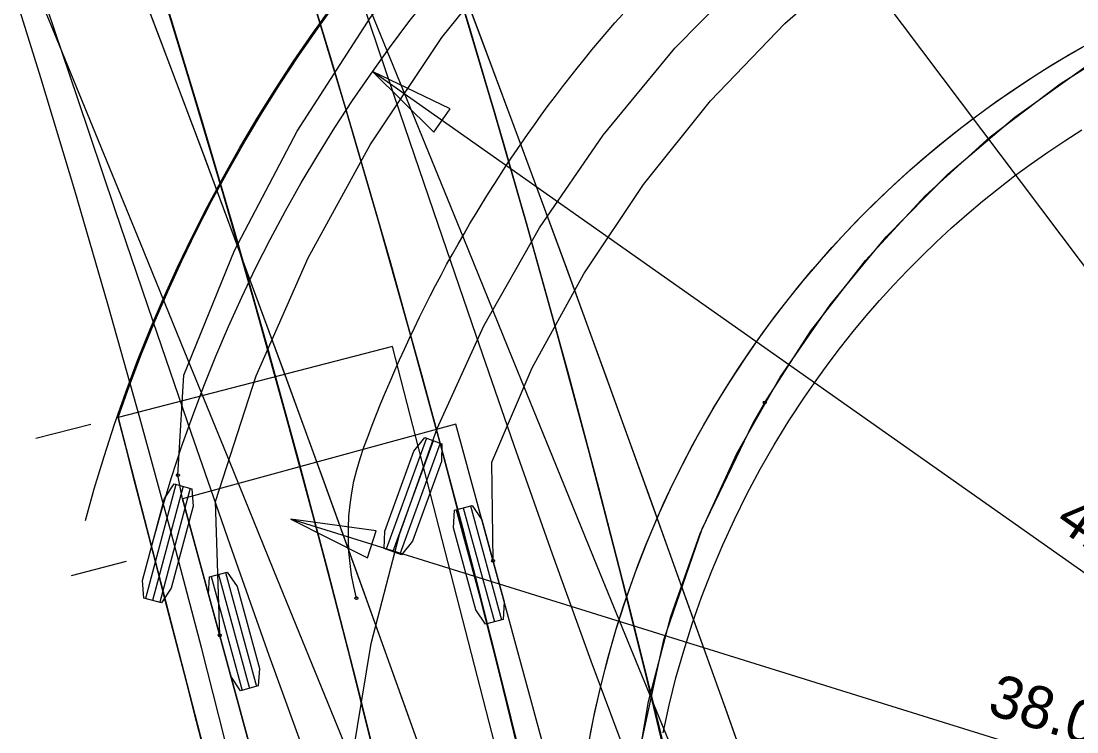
# Model space of a CAD drawing. Extents: x 916040 to 917457, y 328936 to 330267.
# Drawn here: x 916654.52 to 916684.33, y 329799.1 to 329819.17 of the extents above; entities that cross this region are included whole.
import ezdxf

# ---------------------------------------------------------------- set-up
doc = ezdxf.new("R2010")
doc.units = 0
for name, color, linetype in [('EB_LeftontoManchester_WB67', 7, 'Continuous'), ('EB_LeftontoManchester_WB67_v2', 7, 'Continuous'), ('NB_ThruontoManchester_WB67', 7, 'Continuous'), ('SU_IntoDriveway', 7, 'Continuous'), ('SU_IntoDriveway_Rt', 7, 'Continuous'), ('WB_RightontoManchester_WB67', 7, 'Continuous')]:
    doc.layers.add(name, color=color, linetype=linetype)

msp = doc.modelspace()

# ---------------------------------------------------------------- linework, layer by layer
at = {"layer": 'EB_LeftontoManchester_WB67'}
for points in [[(916682.241, 329777.749), (916681.118, 329780.876), (916680, 329784.008), (916678.884, 329787.143), (916677.771, 329790.282), (916676.657, 329793.423), (916675.541, 329796.565), (916674.423, 329799.708), (916673.299, 329802.851), (916672.17, 329805.993), (916671.034, 329809.133), (916669.889, 329812.272), (916668.734, 329815.408), (916667.569, 329818.541), (916666.392, 329821.67), (916665.202, 329824.794), (916663.999, 329827.914), (916662.781, 329831.029), (916661.548, 329834.138), (916660.298, 329837.24), (916659.033, 329840.337), (916657.749, 329843.426)], [(916678.932, 329775.573), (916677.819, 329778.595), (916676.808, 329781.65), (916675.901, 329784.736), (916675.099, 329787.849), (916674.397, 329790.994), (916673.698, 329794.181), (916672.962, 329797.377), (916672.193, 329800.579), (916671.392, 329803.785), (916670.559, 329806.993), (916669.696, 329810.202), (916668.803, 329813.41), (916667.88, 329816.616), (916666.928, 329819.819), (916665.947, 329823.018), (916664.938, 329826.212), (916663.901, 329829.401), (916662.836, 329832.582), (916661.742, 329835.757), (916660.621, 329838.924), (916659.472, 329842.082)], [(916669.601, 329778.228), (916668.593, 329781.538), (916667.695, 329784.881), (916666.908, 329788.244), (916666.151, 329791.57), (916665.373, 329794.873), (916664.574, 329798.156), (916663.752, 329801.421), (916662.906, 329804.669), (916662.034, 329807.902), (916661.138, 329811.12), (916660.215, 329814.324), (916659.267, 329817.515), (916658.293, 329820.694), (916657.292, 329823.861), (916656.265, 329827.016), (916655.212, 329830.159), (916654.132, 329833.291)], [(916673.116, 329778.01), (916671.993, 329781.154), (916670.875, 329784.298), (916669.76, 329787.441), (916668.646, 329790.581), (916667.532, 329793.719), (916666.416, 329796.854), (916665.297, 329799.984), (916664.174, 329803.111), (916663.044, 329806.232), (916661.907, 329809.349), (916660.762, 329812.46), (916659.607, 329815.564), (916658.441, 329818.663), (916657.264, 329821.754), (916656.074, 329824.839), (916654.871, 329827.916), (916653.654, 329830.986)]]:
    msp.add_lwpolyline(points, dxfattribs=at)
msp.add_arc((916291.649, 329706.552), 388, 12.26429, 55.55708, dxfattribs=at)
at = {"layer": 'EB_LeftontoManchester_WB67_v2'}
for points in [[(916682.262, 329777.695), (916681.14, 329780.819), (916680.022, 329783.947), (916678.908, 329787.079), (916677.796, 329790.214), (916676.683, 329793.351), (916675.569, 329796.49), (916674.451, 329799.629), (916673.33, 329802.768), (916672.202, 329805.907), (916671.067, 329809.044), (916669.924, 329812.179), (916668.771, 329815.311), (916667.607, 329818.44), (916666.432, 329821.566), (916665.243, 329824.687), (916664.042, 329827.804), (916662.826, 329830.915), (916661.595, 329834.021), (916660.348, 329837.12), (916659.084, 329840.213), (916657.803, 329843.299)], [(916678.932, 329775.573), (916677.819, 329778.595), (916676.808, 329781.65), (916675.901, 329784.736), (916675.099, 329787.849), (916674.397, 329790.993), (916673.699, 329794.177), (916672.964, 329797.369), (916672.196, 329800.567), (916671.396, 329803.769), (916670.564, 329806.974), (916669.702, 329810.179), (916668.81, 329813.384), (916667.889, 329816.587), (916666.938, 329819.786), (916665.959, 329822.981), (916664.951, 329826.172), (916663.916, 329829.357), (916662.852, 329832.535), (916661.76, 329835.706), (916660.641, 329838.869), (916659.494, 329842.024)], [(916669.601, 329778.228), (916668.593, 329781.538), (916667.695, 329784.881), (916666.908, 329788.244), (916666.152, 329791.565), (916665.375, 329794.865), (916664.577, 329798.144), (916663.756, 329801.406), (916662.911, 329804.65), (916662.04, 329807.879), (916661.145, 329811.094), (916660.224, 329814.294), (916659.277, 329817.482), (916658.304, 329820.657), (916657.305, 329823.82), (916656.28, 329826.972), (916655.228, 329830.112), (916654.15, 329833.241)], [(916673.137, 329777.952), (916672.016, 329781.093), (916670.899, 329784.233), (916669.785, 329787.372), (916668.672, 329790.509), (916667.559, 329793.644), (916666.445, 329796.775), (916665.327, 329799.902), (916664.205, 329803.025), (916663.077, 329806.143), (916661.942, 329809.256), (916660.798, 329812.364), (916659.645, 329815.465), (916658.481, 329818.56), (916657.305, 329821.649), (916656.117, 329824.73), (916654.916, 329827.804), (916653.7, 329830.87)]]:
    msp.add_lwpolyline(points, dxfattribs=at)
msp.add_arc((916291.649, 329706.552), 388, 12.26429, 55.55708, dxfattribs=at)
at = {"layer": 'NB_ThruontoManchester_WB67'}
for points in [[(916658.563, 329844.52), (916659.735, 329841.36), (916660.881, 329838.191), (916661.999, 329835.012), (916663.089, 329831.823), (916664.152, 329828.625), (916665.188, 329825.419), (916666.196, 329822.203), (916667.177, 329818.979), (916668.129, 329815.746), (916669.054, 329812.506), (916669.951, 329809.257), (916670.82, 329806.001), (916671.661, 329802.738), (916672.474, 329799.467), (916673.258, 329796.19), (916674.015, 329792.906), (916674.743, 329789.616), (916675.443, 329786.319), (916676.154, 329783.049), (916676.943, 329779.815), (916677.81, 329776.614)], [(916656.424, 329841.868), (916657.582, 329838.712), (916658.717, 329835.55), (916659.831, 329832.383), (916660.928, 329829.215), (916662.011, 329826.048), (916663.084, 329822.884), (916664.15, 329819.726), (916665.214, 329816.576), (916666.28, 329813.435), (916667.353, 329810.298), (916668.431, 329807.188), (916669.516, 329804.119), (916670.609, 329801.098), (916671.718, 329798.131), (916672.846, 329795.221), (916673.997, 329792.375), (916675.176, 329789.597), (916676.385, 329786.893), (916677.646, 329784.229), (916678.988, 329781.557), (916680.41, 329778.888), (916681.91, 329776.227)], [(916653.456, 329835.216), (916654.549, 329832.101), (916655.615, 329828.976), (916656.654, 329825.843), (916657.666, 329822.7), (916658.651, 329819.549), (916659.609, 329816.39), (916660.54, 329813.223), (916661.443, 329810.047), (916662.319, 329806.865), (916663.168, 329803.674), (916663.989, 329800.477), (916664.783, 329797.272), (916665.549, 329794.061), (916666.287, 329790.844), (916666.998, 329787.62), (916667.681, 329784.39), (916668.391, 329781.119), (916669.189, 329777.848)], [(916653.964, 329823.309), (916655.032, 329820.161), (916656.096, 329817.008), (916657.162, 329813.853), (916658.233, 329810.697), (916659.315, 329807.533), (916660.407, 329804.385), (916661.51, 329801.263), (916662.629, 329798.171), (916663.771, 329795.116), (916664.939, 329792.1), (916666.14, 329789.131), (916667.379, 329786.212), (916668.658, 329783.351), (916670, 329780.514), (916671.433, 329777.661)]]:
    msp.add_lwpolyline(points, dxfattribs=at)
msp.add_arc((916291.649, 329706.552), 388, 11.6689, 55.55708, dxfattribs=at)
at = {"layer": 'SU_IntoDriveway'}
for p, q in [((916698.419, 329793.805), (916672.246, 329828.591)), ((916698.419, 329793.805), (916664.439, 329817.747)), ((916665.004, 329809.975), (916657.257, 329807.977)), ((916672.494, 329780.925), (916665.004, 329809.975)), ((916657.257, 329807.977), (916664.747, 329778.927)), ((916657.257, 329807.977), (916657.257, 329807.977)), ((916656.483, 329807.778), (916654.933, 329807.378)), ((916665.961, 329807.388), (916664.822, 329804.256)), ((916666.157, 329807.317), (916665.017, 329804.185)), ((916666.353, 329807.246), (916665.213, 329804.113)), ((916658.889, 329806.084), (916658.029, 329802.863)), ((916659.09, 329806.03), (916658.23, 329802.809)), ((916659.292, 329805.976), (916658.432, 329802.756)), ((916698.419, 329793.805), (916662.129, 329805.103)), ((916657.481, 329803.904), (916655.932, 329803.505))]:
    msp.add_line(p, q, dxfattribs=at)
for points in [[(916658.258, 329804.527), (916658.503, 329805.405), (916658.767, 329806.277), (916659.05, 329807.143), (916659.352, 329808.003), (916659.672, 329808.856), (916660.012, 329809.702), (916660.369, 329810.54), (916660.745, 329811.37), (916661.14, 329812.192), (916661.552, 329813.005), (916661.982, 329813.809), (916662.429, 329814.603), (916662.894, 329815.387), (916663.375, 329816.16), (916663.874, 329816.923), (916664.389, 329817.675), (916664.921, 329818.415), (916665.468, 329819.144), (916666.032, 329819.86)], [(916658.258, 329804.527), (916658.503, 329805.405), (916658.767, 329806.277), (916659.05, 329807.143), (916659.352, 329808.003), (916659.672, 329808.856), (916660.012, 329809.702), (916660.369, 329810.54), (916660.745, 329811.37), (916661.14, 329812.192), (916661.552, 329813.005), (916661.982, 329813.809), (916662.429, 329814.603), (916662.894, 329815.387), (916663.375, 329816.16), (916663.874, 329816.923), (916664.389, 329817.675), (916664.921, 329818.415), (916665.468, 329819.144), (916666.032, 329819.86)], [(916656.331, 329805.064), (916656.582, 329805.963), (916656.859, 329806.877), (916657.155, 329807.785), (916657.472, 329808.687), (916657.808, 329809.581), (916658.164, 329810.467), (916658.539, 329811.346), (916658.933, 329812.216), (916659.346, 329813.077), (916659.778, 329813.929), (916660.228, 329814.771), (916660.697, 329815.603), (916661.184, 329816.425), (916661.689, 329817.236), (916662.212, 329818.036), (916662.752, 329818.824), (916663.309, 329819.599)], [(916659.611, 329798.847), (916659.397, 329799.677), (916659.183, 329800.507), (916658.969, 329801.337), (916658.755, 329802.167), (916658.541, 329802.997), (916658.327, 329803.827), (916658.113, 329804.657), (916657.899, 329805.487), (916657.685, 329806.317), (916657.471, 329807.147), (916657.257, 329807.977), (916657.257, 329807.977), (916657.578, 329808.876), (916657.918, 329809.768), (916658.278, 329810.652), (916658.657, 329811.528), (916659.055, 329812.395), (916659.472, 329813.254), (916659.907, 329814.103), (916660.362, 329814.942), (916660.834, 329815.772), (916661.325, 329816.59), (916661.833, 329817.398), (916662.359, 329818.194), (916662.902, 329818.979), (916663.463, 329819.752)], [(916670.525, 329798.633), (916670.684, 329799.475), (916670.869, 329800.311), (916671.079, 329801.142), (916671.314, 329801.966), (916671.574, 329802.782), (916671.858, 329803.59), (916672.166, 329804.389), (916672.499, 329805.178), (916672.855, 329805.957), (916673.235, 329806.725), (916673.638, 329807.481), (916674.063, 329808.224), (916674.511, 329808.954), (916674.98, 329809.67), (916674.98, 329809.67), (916674.98, 329809.67), (916675.334, 329810.181), (916675.699, 329810.683), (916676.075, 329811.177), (916676.462, 329811.663), (916676.859, 329812.141), (916677.267, 329812.609), (916677.684, 329813.069), (916678.112, 329813.519), (916678.55, 329813.959), (916678.997, 329814.39), (916679.453, 329814.811), (916679.919, 329815.222), (916680.393, 329815.623), (916680.876, 329816.013), (916681.368, 329816.392), (916681.867, 329816.761), (916682.375, 329817.118), (916682.89, 329817.465), (916683.413, 329817.799), (916683.943, 329818.123), (916684.48, 329818.434)], [(916670.525, 329798.633), (916670.684, 329799.475), (916670.869, 329800.311), (916671.079, 329801.142), (916671.314, 329801.966), (916671.574, 329802.782), (916671.858, 329803.59), (916672.166, 329804.389), (916672.499, 329805.178), (916672.855, 329805.957), (916673.235, 329806.725), (916673.638, 329807.481), (916674.063, 329808.224), (916674.511, 329808.954), (916674.98, 329809.67), (916674.98, 329809.67), (916674.98, 329809.67), (916675.334, 329810.181), (916675.699, 329810.683), (916676.075, 329811.177), (916676.462, 329811.663), (916676.859, 329812.141), (916677.267, 329812.609), (916677.684, 329813.069), (916678.112, 329813.519), (916678.55, 329813.959), (916678.997, 329814.39), (916679.453, 329814.811), (916679.919, 329815.222), (916680.393, 329815.623), (916680.876, 329816.013), (916681.368, 329816.392), (916681.867, 329816.761), (916682.375, 329817.118), (916682.89, 329817.465), (916683.413, 329817.799), (916683.943, 329818.123), (916684.48, 329818.434)], [(916670.6, 329799.048), (916670.722, 329799.657), (916670.857, 329800.263), (916671.006, 329800.866), (916671.168, 329801.465), (916671.343, 329802.061), (916671.53, 329802.652), (916671.731, 329803.24), (916671.945, 329803.822), (916672.171, 329804.4), (916672.41, 329804.973), (916672.661, 329805.541), (916672.925, 329806.103), (916673.201, 329806.659), (916673.489, 329807.208), (916673.789, 329807.752), (916674.101, 329808.288), (916674.425, 329808.818), (916674.76, 329809.34), (916675.107, 329809.855), (916675.464, 329810.362), (916675.833, 329810.862), (916676.213, 329811.353), (916676.603, 329811.835), (916677.004, 329812.309), (916677.415, 329812.774), (916677.836, 329813.23), (916678.267, 329813.677), (916678.707, 329814.114), (916679.157, 329814.541), (916679.617, 329814.958), (916680.085, 329815.365), (916680.563, 329815.762), (916681.048, 329816.148), (916681.542, 329816.523), (916682.045, 329816.888), (916682.555, 329817.241), (916683.073, 329817.583), (916683.598, 329817.914), (916684.13, 329818.233), (916684.669, 329818.54)], [(916672.644, 329799.073), (916672.815, 329799.851), (916673.01, 329800.622), (916673.229, 329801.388), (916673.47, 329802.147), (916673.734, 329802.898), (916674.021, 329803.64), (916674.33, 329804.374), (916674.662, 329805.098), (916675.014, 329805.811), (916675.389, 329806.514), (916675.784, 329807.204), (916676.2, 329807.883), (916676.639, 329808.552), (916676.965, 329809.023), (916677.304, 329809.49), (916677.654, 329809.949), (916678.013, 329810.401), (916678.382, 329810.844), (916678.761, 329811.28), (916679.149, 329811.707), (916679.547, 329812.125), (916679.954, 329812.535), (916680.369, 329812.935), (916680.793, 329813.327), (916681.226, 329813.708), (916681.667, 329814.081), (916682.116, 329814.443), (916682.572, 329814.796), (916683.037, 329815.138), (916683.508, 329815.47), (916683.987, 329815.792), (916684.473, 329816.103)]]:
    msp.add_lwpolyline(points, dxfattribs=at)
for points in [[(916664.439, 329817.747), (916666.17, 329816.037), (916666.631, 329816.691)], [(916665.913, 329807.406), (916666.402, 329807.228), (916666.389, 329806.736), (916665.569, 329804.481), (916665.262, 329804.096), (916664.773, 329804.274), (916664.785, 329804.766), (916665.606, 329807.021)], [(916658.839, 329806.097), (916659.342, 329805.963), (916659.373, 329805.472), (916658.753, 329803.153), (916658.482, 329802.742), (916657.979, 329802.876), (916657.948, 329803.368), (916658.567, 329805.687)], [(916662.129, 329805.103), (916664.302, 329804.007), (916664.54, 329804.771)]]:
    msp.add_lwpolyline(points, close=True, dxfattribs=at)
at = {"layer": 'SU_IntoDriveway_Rt'}
for p, q in [((916666.793, 329807.782), (916659.074, 329805.681)), ((916674.672, 329778.835), (916666.793, 329807.782)), ((916659.074, 329805.681), (916666.953, 329776.734)), ((916659.074, 329805.681), (916659.074, 329805.681)), ((916667.205, 329805.476), (916668.081, 329802.26)), ((916666.803, 329805.367), (916667.679, 329802.15)), ((916667.004, 329805.421), (916667.88, 329802.205)), ((916659.888, 329803.485), (916660.763, 329800.268)), ((916660.089, 329803.539), (916660.964, 329800.323)), ((916660.29, 329803.594), (916661.165, 329800.378))]:
    msp.add_line(p, q, dxfattribs=at)
for points in [[(916660.125, 329801.822), (916660.008, 329805.599), (916661.156, 329809.15), (916662.624, 329812.483), (916664.377, 329815.676), (916666.401, 329818.705), (916668.682, 329821.545), (916671.201, 329824.176), (916673.94, 329826.578), (916676.877, 329828.732), (916679.991, 329830.621), (916683.258, 329832.233), (916686.652, 329833.554), (916690.149, 329834.574), (916693.721, 329835.285), (916697.342, 329835.683), (916700.984, 329835.764), (916704.619, 329835.527), (916708.219, 329834.975), (916708.933, 329834.827)], [(916658.946, 329806.345), (916659.114, 329809.168), (916660.538, 329812.688), (916662.316, 329816.062), (916664.382, 329819.268), (916666.719, 329822.282), (916669.31, 329825.082), (916672.135, 329827.644), (916675.172, 329829.952), (916676.441, 329830.799)], [(916665.377, 329782.524), (916664.541, 329785.79), (916663.959, 329788.933), (916663.656, 329792.099), (916663.629, 329795.28), (916663.88, 329798.451), (916664.406, 329801.588), (916665.203, 329804.667), (916666.265, 329807.666), (916667.584, 329810.56), (916669.151, 329813.328), (916670.952, 329815.95), (916672.975, 329818.404), (916675.205, 329820.673), (916677.623, 329822.739), (916680.212, 329824.587), (916682.952, 329826.202), (916685.823, 329827.572), (916688.802, 329828.687), (916689.409, 329828.879)], [(916667.844, 329803.923), (916667.812, 329806.71), (916668.948, 329809.381), (916670.407, 329812.035), (916672.091, 329814.552), (916673.988, 329816.913), (916676.084, 329819.099), (916678.362, 329821.095), (916680.805, 329822.884), (916683.394, 329824.454), (916686.111, 329825.793), (916688.934, 329826.889), (916691.841, 329827.736), (916694.812, 329828.326), (916697.822, 329828.655), (916700.85, 329828.721), (916703.872, 329828.523), (916706.865, 329828.062), (916709.807, 329827.343), (916710.387, 329827.168)], [(916673.096, 329784.625), (916672.333, 329787.599), (916671.878, 329790.074), (916671.643, 329792.546), (916671.625, 329795.029), (916671.824, 329797.505), (916672.237, 329799.953), (916672.862, 329802.357), (916673.694, 329804.697), (916674.726, 329806.955), (916675.951, 329809.115), (916677.36, 329811.16), (916678.942, 329813.075), (916680.684, 329814.844), (916682.574, 329816.455), (916684.597, 329817.895), (916686.738, 329819.154), (916688.98, 329820.221), (916691.307, 329821.089), (916691.78, 329821.239)], [(916675.516, 329808.395), (916676.819, 329810.418), (916678.359, 329812.408), (916680.046, 329814.231), (916681.885, 329815.9), (916683.862, 329817.402), (916685.962, 329818.727), (916688.17, 329819.863), (916690.469, 329820.803), (916691.41, 329821.122)], [(916663.984, 329802.872), (916663.91, 329803.197), (916663.851, 329803.525), (916663.805, 329803.855), (916663.775, 329804.187), (916663.759, 329804.52), (916663.759, 329804.854), (916663.774, 329805.187), (916663.805, 329805.519), (916663.852, 329805.849), (916663.914, 329806.176), (916663.993, 329806.5), (916664.088, 329806.819), (916664.199, 329807.134), (916664.315, 329807.446), (916664.433, 329807.758), (916664.555, 329808.068), (916664.679, 329808.378), (916664.806, 329808.686), (916664.935, 329808.993), (916665.067, 329809.299), (916665.202, 329809.604), (916665.339, 329809.908), (916665.48, 329810.21), (916665.622, 329810.511), (916665.768, 329810.811), (916665.916, 329811.11), (916666.066, 329811.407), (916666.219, 329811.703), (916666.375, 329811.998), (916666.533, 329812.292), (916666.694, 329812.583), (916666.858, 329812.874), (916667.024, 329813.163), (916667.192, 329813.451), (916667.363, 329813.737), (916667.536, 329814.022), (916667.712, 329814.305), (916667.891, 329814.586), (916668.071, 329814.866), (916668.255, 329815.145), (916668.44, 329815.422), (916668.628, 329815.697), (916668.819, 329815.97), (916669.012, 329816.242), (916669.207, 329816.512), (916669.404, 329816.781), (916669.604, 329817.048), (916669.807, 329817.313), (916670.011, 329817.576), (916670.218, 329817.837), (916670.427, 329818.097), (916670.638, 329818.355), (916670.852, 329818.611), (916671.068, 329818.865), (916671.286, 329819.117), (916671.506, 329819.367)], [(916674.672, 329778.835), (916673.797, 329782.052), (916672.922, 329785.268), (916672.14, 329788.508), (916671.691, 329791.807), (916671.63, 329795.135), (916671.957, 329798.445), (916672.667, 329801.693), (916673.75, 329804.834), (916675.191, 329807.827), (916675.191, 329807.827), (916675.191, 329807.827), (916675.516, 329808.395)], [(916666.953, 329776.734), (916665.944, 329779.917), (916664.801, 329783.092), (916663.977, 329786.352), (916663.451, 329789.6), (916662.576, 329792.816), (916661.7, 329796.032), (916660.825, 329799.249), (916659.95, 329802.465), (916659.074, 329805.681), (916659.074, 329805.681), (916658.946, 329806.345)]]:
    msp.add_lwpolyline(points, dxfattribs=at)
for points in [[(916666.753, 329805.353), (916667.255, 329805.49), (916667.529, 329805.081), (916668.159, 329802.765), (916668.13, 329802.273), (916667.629, 329802.137), (916667.355, 329802.546), (916666.725, 329804.862)], [(916659.838, 329803.471), (916660.34, 329803.608), (916660.614, 329803.198), (916661.244, 329800.883), (916661.215, 329800.391), (916660.714, 329800.255), (916660.44, 329800.664), (916659.81, 329802.98)]]:
    msp.add_lwpolyline(points, close=True, dxfattribs=at)
for centre in [(916675.516, 329808.395), (916675.516, 329808.395), (916658.946, 329806.345), (916658.946, 329806.345), (916667.844, 329803.923), (916663.984, 329802.872), (916660.125, 329801.822)]:
    msp.add_circle(centre, 0.0417, dxfattribs=at)
at = {"layer": 'WB_RightontoManchester_WB67'}
for points in [[(916682.431, 329776.405), (916681.081, 329779.393), (916679.751, 329782.399), (916678.437, 329785.421), (916677.138, 329788.456), (916675.851, 329791.503), (916674.574, 329794.56), (916673.306, 329797.625), (916672.043, 329800.697), (916670.785, 329803.775), (916669.529, 329806.857), (916668.273, 329809.942), (916667.016, 329813.029), (916665.756, 329816.117), (916664.492, 329819.205), (916663.221, 329822.292), (916661.943, 329825.378), (916660.657, 329828.461), (916659.361, 329831.542), (916658.054, 329834.618), (916656.736, 329837.69), (916655.404, 329840.757), (916654.059, 329843.818)], [(916675.571, 329775.79), (916674.221, 329778.778), (916673.014, 329781.811), (916671.952, 329784.886), (916671.034, 329787.997), (916670.261, 329791.139), (916669.556, 329794.318), (916668.814, 329797.507), (916668.038, 329800.703), (916667.229, 329803.904), (916666.388, 329807.107), (916665.516, 329810.311), (916664.613, 329813.515), (916663.681, 329816.716), (916662.719, 329819.915), (916661.727, 329823.11), (916660.707, 329826.3), (916659.659, 329829.484), (916658.582, 329832.661), (916657.477, 329835.831), (916656.343, 329838.994), (916655.182, 329842.148)], [(916673.323, 329775.921), (916671.967, 329778.983), (916670.633, 329782.053), (916669.316, 329785.129), (916668.014, 329788.211), (916666.726, 329791.297), (916665.448, 329794.384), (916664.178, 329797.474), (916662.915, 329800.563), (916661.657, 329803.651), (916660.4, 329806.738), (916659.144, 329809.822), (916657.887, 329812.902), (916656.628, 329815.979), (916655.364, 329819.051), (916654.094, 329822.118)], [(916665.856, 329778.266), (916664.698, 329781.552), (916663.682, 329784.894), (916662.813, 329788.286), (916662.041, 329791.623), (916661.252, 329794.929), (916660.442, 329798.214), (916659.609, 329801.48), (916658.752, 329804.729), (916657.87, 329807.961), (916656.962, 329811.178), (916656.029, 329814.381), (916655.07, 329817.571), (916654.084, 329820.747)]]:
    msp.add_lwpolyline(points, dxfattribs=at)
msp.add_arc((916291.649, 329706.552), 384, 12.55823, 55.55708, dxfattribs=at)

# ---------------------------------------------------------------- texts
at = {"layer": 'SU_IntoDriveway'}
for s, rotation, p in [('41.6 ft', 324.8319, (916683.665, 329804.934)), ('38.0 ft', 342.7069, (916681.763, 329799.618))]:
    msp.add_text(s, height=1.2, rotation=rotation, dxfattribs=at).set_placement(p)

doc.saveas('drawing.dxf')
